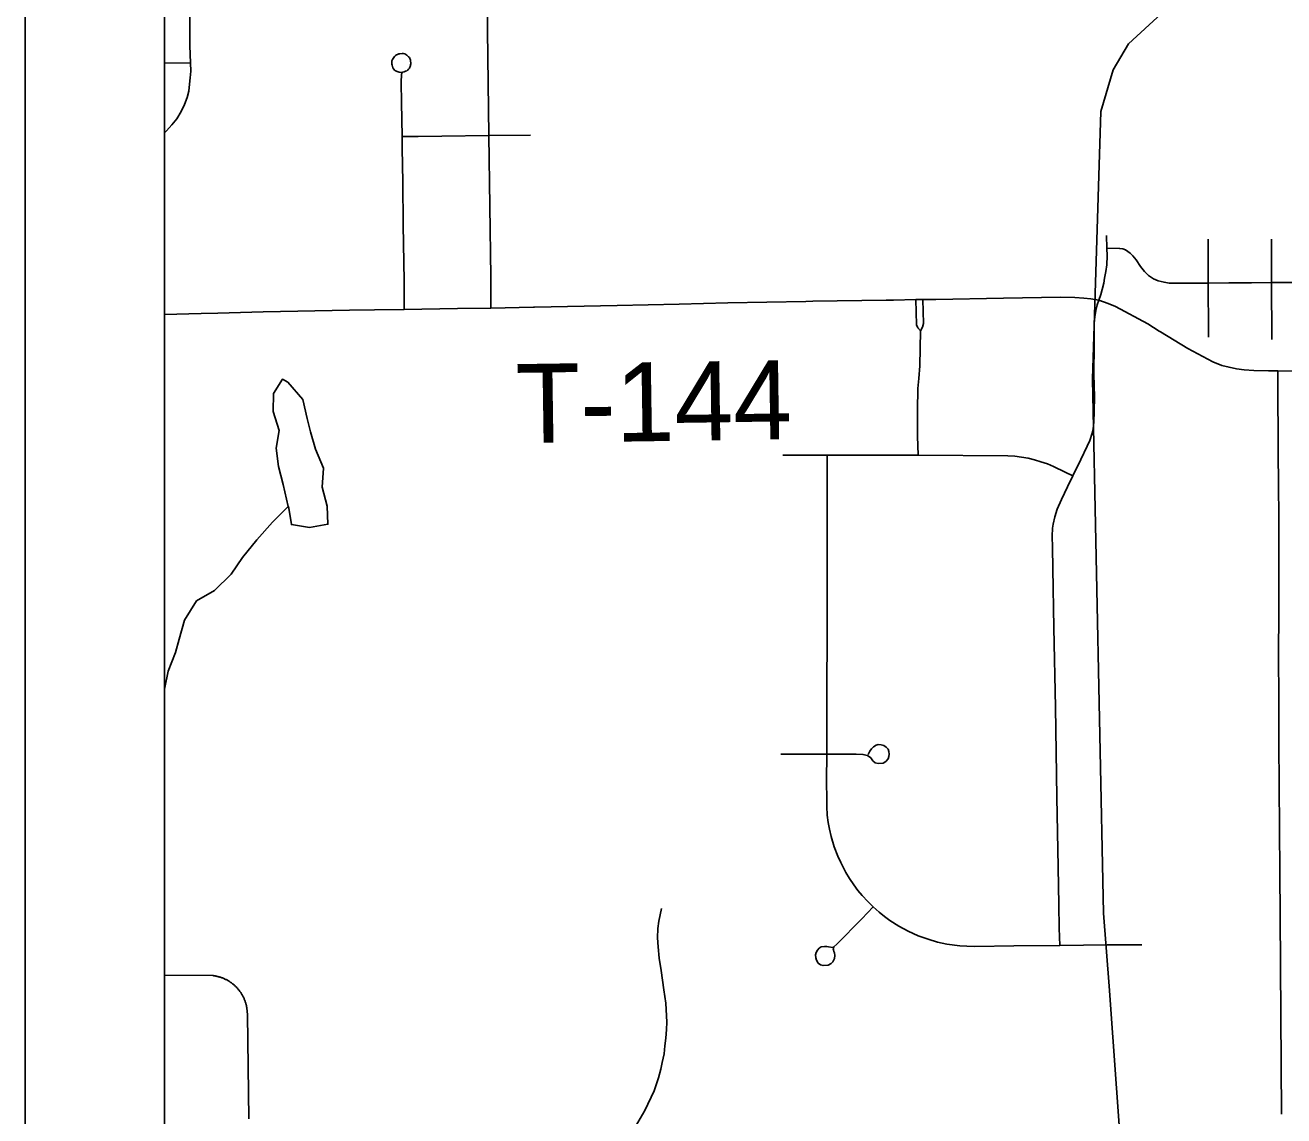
# Model space of a CAD drawing. Extents: x 0 to 34, y -5 to 22.
# Drawn here: x 2 to 2.904, y 17.236 to 18.02 of the extents above; entities that cross this region are included whole.
import ezdxf

# ---------------------------------------------------------------- set-up
doc = ezdxf.new("R2010")
doc.units = 0
for name, color, linetype in [('GM_X_City_Street', 7, 'Continuous'), ('GM_X_Minor_Lake', 7, 'Continuous'), ('GM_X_Minor_River', 7, 'Continuous'), ('GM_X_Rail_Line', 7, 'Continuous'), ('GM_X_Township_Road', 7, 'Continuous'), ('GM_X_Township_Road_Text', 7, 'Continuous'), ('GM_X_US_Route', 7, 'Continuous'), ('SH_Cut_Line', 7, 'Continuous'), ('SH_Data', 7, 'Continuous')]:
    doc.layers.add(name, color=color, linetype=linetype)

msp = doc.modelspace()

# ---------------------------------------------------------------- linework, layer by layer
at = {"layer": 'GM_X_City_Street'}
msp.add_line((2.1, 17.99249), (2.11876, 17.99282), dxfattribs=at)
for points in [[(2.33469, 17.8165), (2.33463, 17.83885), (2.33306, 17.94047), (2.33231, 18.01609), (2.33145, 18.09827), (2.3308, 18.12632), (2.32921, 18.22126), (2.32947, 18.2242), (2.32905, 18.22712), (2.3281, 18.23297), (2.32724, 18.23709), (2.32569, 18.24207), (2.32432, 18.24741), (2.32406, 18.25067), (2.32423, 18.25548), (2.32398, 18.26692), (2.3238, 18.29262), (2.32329, 18.34299), (2.32311, 18.37445), (2.32281, 18.39601)], [(2.1, 17.9424), (2.10157, 17.94384), (2.10544, 17.94811), (2.10906, 17.95247), (2.11218, 17.95781), (2.1144, 17.96274), (2.11629, 17.96784), (2.11753, 17.97244), (2.11813, 17.97747), (2.11867, 17.98189), (2.11892, 17.98682), (2.11876, 17.99282), (2.11843, 18.00499), (2.11826, 18.02349), (2.11785, 18.03951), (2.11701, 18.05933), (2.11654, 18.10125), (2.1157, 18.12687), (2.11555, 18.15115), (2.11423, 18.16956), (2.11349, 18.17104)], [(2.27241, 17.81559), (2.27226, 17.83588), (2.27156, 17.87627), (2.27127, 17.90692), (2.27092, 17.93151), (2.27086, 17.93977), (2.27046, 17.96438), (2.27028, 17.97866), (2.27044, 17.98457), (2.27055, 17.98508), (2.27066, 17.98544), (2.27086, 17.98575), (2.27108, 17.98599), (2.27148, 17.98614), (2.27233, 17.98639), (2.27325, 17.98672), (2.27417, 17.98715), (2.27466, 17.98746), (2.27517, 17.98783), (2.27553, 17.98824), (2.27585, 17.98862), (2.2761, 17.98905), (2.27635, 17.98958), (2.27659, 17.99018), (2.27681, 17.99085), (2.27694, 17.99132), (2.2771, 17.99214), (2.27688, 17.99464), (2.27657, 17.99553), (2.27633, 17.996), (2.27605, 17.99655), (2.27552, 17.9972), (2.27504, 17.99766), (2.27421, 17.99832), (2.27343, 17.99882), (2.2727, 17.99915), (2.27187, 17.99939), (2.27099, 17.99949), (2.26918, 17.99937), (2.26841, 17.99917), (2.26755, 17.99882), (2.26678, 17.99842), (2.26609, 17.99797), (2.26539, 17.99735), (2.26488, 17.99672), (2.26438, 17.99599), (2.26392, 17.99512), (2.26358, 17.99428), (2.26346, 17.99348), (2.26352, 17.99184), (2.26366, 17.99103), (2.26392, 17.99013), (2.26422, 17.98925), (2.2648, 17.98828), (2.26536, 17.98761), (2.26606, 17.98706), (2.26676, 17.9867), (2.26737, 17.98647), (2.26874, 17.9861), (2.27057, 17.98573)], [(2.27086, 17.93977), (2.28228, 17.93991), (2.2995, 17.94017), (2.33306, 17.94047), (2.36311, 17.94074)], [(2.74341, 17.35842), (2.74305, 17.37078), (2.74269, 17.38764), (2.74239, 17.41456), (2.74129, 17.46495), (2.74024, 17.52956), (2.73919, 17.58668), (2.7384, 17.62935), (2.73822, 17.64451), (2.73801, 17.65266), (2.73827, 17.65822), (2.73875, 17.6612), (2.73989, 17.66637), (2.74155, 17.67198), (2.74462, 17.6789), (2.74904, 17.68792), (2.75291, 17.69593), (2.75862, 17.70757), (2.76315, 17.71714), (2.76504, 17.72122), (2.76666, 17.7266), (2.76735, 17.72976), (2.76797, 17.73453), (2.76825, 17.74224), (2.76841, 17.75267), (2.76797, 17.76875), (2.76823, 17.79039), (2.76814, 17.80563), (2.76858, 17.81032), (2.76924, 17.8147), (2.77034, 17.81887), (2.77142, 17.82215), (2.77288, 17.82622), (2.77393, 17.82994), (2.77498, 17.83446), (2.77568, 17.83803), (2.7766, 17.8427), (2.77717, 17.84769), (2.77739, 17.85408), (2.77726, 17.85969), (2.77707, 17.86861)], [(2.85033, 17.79559), (2.85022, 17.80992), (2.85011, 17.8238), (2.85002, 17.83441), (2.8501, 17.86603)], [(2.89582, 17.79381), (2.89573, 17.80574), (2.89559, 17.8241), (2.89551, 17.83488), (2.89551, 17.86603)], [(2.77726, 17.85969), (2.7864, 17.85945), (2.78879, 17.85899), (2.79066, 17.85836), (2.79244, 17.85727), (2.79407, 17.85604), (2.79586, 17.8541), (2.79835, 17.85111), (2.80136, 17.8465), (2.80423, 17.84278), (2.80725, 17.83992), (2.81066, 17.83759), (2.81407, 17.83612), (2.81832, 17.83511), (2.82213, 17.83449), (2.82972, 17.83434), (2.85002, 17.83441), (2.86498, 17.83457), (2.88125, 17.83474), (2.89551, 17.83488), (2.94087, 17.835)], [(2.64328, 17.80026), (2.64138, 17.80227), (2.64038, 17.80437), (2.63997, 17.82256)], [(2.64328, 17.80026), (2.64478, 17.80277), (2.64539, 17.80537), (2.64493, 17.82261)], [(2.64158, 17.71067), (2.64128, 17.7244), (2.64108, 17.74324), (2.64148, 17.75877), (2.64208, 17.76589), (2.64298, 17.77511), (2.64328, 17.80026)], [(2.54451, 17.71075), (2.56696, 17.71086), (2.57633, 17.71082), (2.63293, 17.7107), (2.64158, 17.71067), (2.70618, 17.71028), (2.71104, 17.70996), (2.7159, 17.70927), (2.72076, 17.70854), (2.72531, 17.70742), (2.72991, 17.70589), (2.73451, 17.70447), (2.739, 17.70256), (2.74735, 17.69865), (2.75291, 17.69593)], [(2.80237, 17.35886), (2.77758, 17.35872), (2.74341, 17.35842), (2.71052, 17.35805), (2.68234, 17.35768), (2.6766, 17.3579), (2.67151, 17.35813), (2.66224, 17.35937), (2.65547, 17.36077), (2.64892, 17.36284), (2.64178, 17.36534), (2.63449, 17.36858), (2.62773, 17.37233), (2.62132, 17.37631), (2.61745, 17.37907), (2.61364, 17.38219), (2.60944, 17.38603), (2.60542, 17.38992), (2.60137, 17.39426), (2.59821, 17.39794), (2.59534, 17.40192), (2.59232, 17.40656), (2.58975, 17.41082), (2.58599, 17.41796), (2.58386, 17.4226), (2.58143, 17.42937), (2.57915, 17.43673), (2.57805, 17.44203), (2.57694, 17.44681), (2.5762, 17.45211), (2.57598, 17.45822), (2.57591, 17.48118), (2.57606, 17.49157), (2.57606, 17.49586), (2.57598, 17.51349), (2.5762, 17.61057), (2.57628, 17.62978), (2.5762, 17.69477), (2.57633, 17.71082)], [(2.54291, 17.49586), (2.57606, 17.49586), (2.59718, 17.49575), (2.60199, 17.49567), (2.60529, 17.49496), (2.60757, 17.49316), (2.6092, 17.49112), (2.61086, 17.48962), (2.61296, 17.48917), (2.61642, 17.48947), (2.61837, 17.49052), (2.62003, 17.49247), (2.62055, 17.49413), (2.62078, 17.49586), (2.62055, 17.49788), (2.62003, 17.49954), (2.6186, 17.50097), (2.61694, 17.5021), (2.61506, 17.50254), (2.61296, 17.50277), (2.61146, 17.50232), (2.60958, 17.50119), (2.60823, 17.49969), (2.60702, 17.49811), (2.60575, 17.4957)], [(2.58028, 17.3568), (2.57736, 17.35736), (2.57593, 17.35765), (2.57429, 17.35761), (2.57203, 17.35731), (2.57057, 17.3565), (2.56927, 17.35505), (2.56841, 17.35334), (2.56791, 17.35153), (2.56806, 17.34937), (2.56861, 17.34776), (2.56982, 17.34575), (2.57153, 17.34439), (2.57339, 17.34394), (2.5769, 17.34429), (2.57912, 17.34545), (2.58032, 17.34671), (2.58148, 17.34902), (2.58168, 17.35105), (2.58148, 17.35299), (2.58114, 17.35407), (2.58078, 17.35522), (2.58068, 17.35588), (2.58072, 17.35668), (2.58115, 17.35731), (2.58314, 17.35927), (2.60117, 17.37741), (2.60944, 17.38603)]]:
    msp.add_lwpolyline(points, dxfattribs=at)
at = {"layer": 'GM_X_Minor_Lake'}
for points in [[(2.18868, 17.76317), (2.18486, 17.76541), (2.17851, 17.75507), (2.17827, 17.74213), (2.18261, 17.72848), (2.18047, 17.7159), (2.18213, 17.7026), (2.18532, 17.6897), (2.18906, 17.67396)], [(2.18906, 17.67396), (2.18938, 17.67271), (2.19134, 17.66085), (2.20429, 17.65871), (2.21757, 17.66114), (2.21704, 17.67408), (2.21347, 17.68773), (2.21446, 17.70144), (2.2086, 17.71507), (2.20504, 17.72759), (2.20266, 17.73708), (2.19946, 17.75074), (2.18868, 17.76317)], [(2.18911, 17.67398), (2.18938, 17.67271), (2.19134, 17.66085), (2.20429, 17.65871), (2.21757, 17.66114), (2.21704, 17.67408), (2.21347, 17.68773), (2.21446, 17.70144), (2.2086, 17.71507), (2.20504, 17.72759), (2.20266, 17.73708), (2.19946, 17.75074), (2.18868, 17.76317)]]:
    msp.add_lwpolyline(points, dxfattribs=at)
at = {"layer": 'GM_X_Minor_River'}
msp.add_lwpolyline([(2.18909, 17.67394), (2.17764, 17.66259), (2.16638, 17.64991), (2.15625, 17.63724), (2.14803, 17.62535), (2.13599, 17.61342), (2.12315, 17.60604), (2.11456, 17.59225), (2.11054, 17.5785), (2.10798, 17.56896), (2.10281, 17.55559), (2.1, 17.54262)], dxfattribs=at)
at = {"layer": 'GM_X_Rail_Line'}
msp.add_lwpolyline([(2.87145, 18.0583), (2.84238, 18.0452), (2.8166, 18.02834), (2.7928, 18.00652), (2.7819, 17.98768), (2.77297, 17.95792), (2.76702, 17.76551), (2.77496, 17.38168), (2.77892, 17.32911), (2.78686, 17.21902), (2.7736, 17.13639), (2.77545, 17.09293)], dxfattribs=at)
at = {"layer": 'GM_X_Township_Road'}
for points in [[(2.25095, 17.81532), (2.27241, 17.81559), (2.31077, 17.81626), (2.33469, 17.8165), (2.36535, 17.81719)], [(2.36535, 17.81719), (2.36607, 17.8172), (2.42531, 17.81848), (2.46998, 17.81941), (2.50498, 17.82016), (2.56105, 17.82133), (2.56597, 17.8214)], [(2.56597, 17.8214), (2.61871, 17.82223), (2.62396, 17.82231)], [(2.62396, 17.82231), (2.63997, 17.82256), (2.64493, 17.82261), (2.65444, 17.82277), (2.70298, 17.82355), (2.7439, 17.82445), (2.7542, 17.82422), (2.76075, 17.82374), (2.76571, 17.82316), (2.77142, 17.82215), (2.77831, 17.8198), (2.78341, 17.81754), (2.80663, 17.80507), (2.81494, 17.79994), (2.81573, 17.79947)], [(2.1, 17.81194), (2.12651, 17.8126), (2.13833, 17.8129)], [(2.13833, 17.8129), (2.17106, 17.8138), (2.23298, 17.81493), (2.25095, 17.81532)], [(2.81573, 17.79947), (2.83555, 17.78742), (2.85334, 17.77798), (2.85985, 17.77525), (2.86504, 17.77397), (2.87043, 17.77283), (2.87585, 17.77217), (2.88291, 17.7717), (2.89344, 17.77135), (2.9001, 17.77139), (2.91209, 17.77127), (2.96472, 17.77142), (3.044, 17.77135), (3.1129, 17.77077), (3.15843, 17.77026), (3.17188, 17.77006), (3.17801, 17.77018)], [(2.9027, 17.23712), (2.90173, 17.37971), (2.90152, 17.41116), (2.90111, 17.4733), (2.90092, 17.50393), (2.90072, 17.53497), (2.90054, 17.56761), (2.90075, 17.59753), (2.90086, 17.61642), (2.90094, 17.63), (2.90074, 17.65916), (2.90049, 17.69618), (2.90043, 17.70607), (2.9001, 17.77139)], [(2.41637, 17.19386), (2.42254, 17.20396), (2.43697, 17.22536), (2.44522, 17.23972), (2.45197, 17.25393), (2.45374, 17.25884), (2.45502, 17.26324), (2.45673, 17.2695), (2.45779, 17.27427), (2.45907, 17.28059), (2.45965, 17.28613), (2.46035, 17.29182), (2.46078, 17.29808), (2.46107, 17.30327), (2.46035, 17.31691), (2.45901, 17.32637), (2.45694, 17.34044), (2.45566, 17.34918), (2.45481, 17.35729), (2.45431, 17.36397), (2.4546, 17.37065), (2.45538, 17.37584), (2.4573, 17.38494)], [(2.16072, 17.23367), (2.15964, 17.30881), (2.15931, 17.31319), (2.15923, 17.31367), (2.15914, 17.31415), (2.15905, 17.31463), (2.15894, 17.31511), (2.15883, 17.31558), (2.15871, 17.31605), (2.15858, 17.31653), (2.15844, 17.317), (2.1583, 17.31746), (2.15814, 17.31792), (2.15798, 17.31838), (2.15781, 17.31884), (2.15763, 17.3193), (2.15745, 17.31975), (2.15726, 17.3202), (2.15706, 17.32064), (2.15685, 17.32109), (2.15663, 17.32152), (2.15641, 17.32196), (2.15618, 17.32238), (2.15594, 17.32281), (2.1557, 17.32324), (2.15544, 17.32365), (2.15518, 17.32407), (2.15491, 17.32447), (2.15463, 17.32488), (2.15435, 17.32527), (2.15406, 17.32567), (2.15377, 17.32606), (2.15347, 17.32644), (2.15315, 17.32682), (2.15284, 17.32719), (2.15252, 17.32756), (2.15219, 17.32792), (2.15186, 17.32828), (2.15151, 17.32862), (2.15117, 17.32897), (2.15081, 17.32931), (2.15046, 17.32964), (2.15009, 17.32997), (2.14972, 17.33028), (2.14935, 17.33059), (2.14897, 17.3309), (2.14857, 17.3312), (2.14818, 17.33149), (2.14779, 17.33177), (2.14739, 17.33205), (2.14698, 17.33232), (2.14657, 17.33259), (2.14616, 17.33284), (2.14574, 17.33309), (2.14531, 17.33333), (2.14488, 17.33357), (2.14445, 17.3338), (2.14401, 17.33402), (2.14357, 17.33423), (2.14313, 17.33443), (2.14268, 17.33463), (2.14224, 17.33482), (2.14178, 17.335), (2.14132, 17.33517), (2.14086, 17.33533), (2.1404, 17.33549), (2.13994, 17.33564), (2.13947, 17.33578), (2.139, 17.33591), (2.13853, 17.33604), (2.13805, 17.33615), (2.13758, 17.33626), (2.1371, 17.33636), (2.13662, 17.33645), (2.13614, 17.33653), (2.13565, 17.33661), (2.13517, 17.33667), (2.10023, 17.33713), (2.1, 17.33713)]]:
    msp.add_lwpolyline(points, dxfattribs=at)
at = {"layer": 'GM_X_US_Route'}
msp.add_lwpolyline([(2.1, 20.9), (2.1, 16.52208), (2.11121, 16.52239), (2.1454, 16.52285), (2.18578, 16.52321), (2.20518, 16.52365), (2.27585, 16.52521), (2.35351, 16.52726), (2.44044, 16.52894), (2.50559, 16.53023), (2.54594, 16.53119), (2.57391, 16.53154), (2.58249, 16.53166), (2.62051, 16.53222), (2.70129, 16.53304), (2.86594, 16.53499), (2.90622, 16.53565)], dxfattribs=at)
at = {"layer": 'SH_Cut_Line'}
msp.add_lwpolyline([(2.1, 20.9), (2.1, 16.52208), (2.11121, 16.52239), (2.1454, 16.52285), (2.18578, 16.52321), (2.20518, 16.52365), (2.27585, 16.52521), (2.35351, 16.52726), (2.44044, 16.52894), (2.50559, 16.53023), (2.54594, 16.53119), (2.57391, 16.53154), (2.58249, 16.53166), (2.62051, 16.53222), (2.70129, 16.53304), (2.86594, 16.53499), (2.90622, 16.53565)], dxfattribs=at)
at = {"layer": 'SH_Data'}
for p, q in [((2, 21), (2, 14)), ((2.1, 20.9), (2.1, 14.1))]:
    msp.add_line(p, q, dxfattribs=at)

# ---------------------------------------------------------------- texts
at = {"layer": 'GM_X_Township_Road_Text'}
msp.add_text('T-144', height=0.056818, rotation=0.84207, dxfattribs=at).set_placement((2.35289, 17.71939))

doc.saveas('drawing.dxf')
